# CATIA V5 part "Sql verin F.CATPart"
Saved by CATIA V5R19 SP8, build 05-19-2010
Part number: Sql verin F
Publications: "Droite.1", "Droite.2", "Plan.2", "Point.3"
Bounding box of the stored display mesh (mm): x 100 to 400, y 50 to 90, z -200 to 0
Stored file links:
  C:\Users\ThinkMotion\Desktop\EU_thinkMotion\iao\IAO_MMS_Groupe3\rdalborgo\rdalborgo\Sql verin F.CATPart
  C:\Users\ThinkMotion\Desktop\EU_thinkMotion\iao\IAO_MMS_Groupe3\rdalborgo\rdalborgo\Sql train.CATProduct
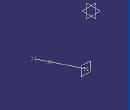
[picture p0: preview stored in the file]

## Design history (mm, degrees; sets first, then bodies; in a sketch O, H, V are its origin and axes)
External parameters (linked from other documents)
  `External.L verin` = 250.0382 mm
Set1
  Point1 "D verin": linked copy from another document
  Point2 "B verin": linked copy from another document
  Plane1: linked copy from another document
Set2
  Line1: type PtPt, FirstPoint Point1, SecondPoint Point2
  Line2: type Normal, RefPoint Point1, RefSkin Plane1, Start -20, End 20
  Plane2: type OffsetPt, RefPlane Plane1, RefPoint Point1
  Point3: type OnCurve, Support Line1, Length 250.0382 {= `External.L verin`}
Body1 (main body)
